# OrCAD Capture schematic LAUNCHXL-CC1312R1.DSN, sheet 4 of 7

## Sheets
4 3_Debugger Interface: size A3
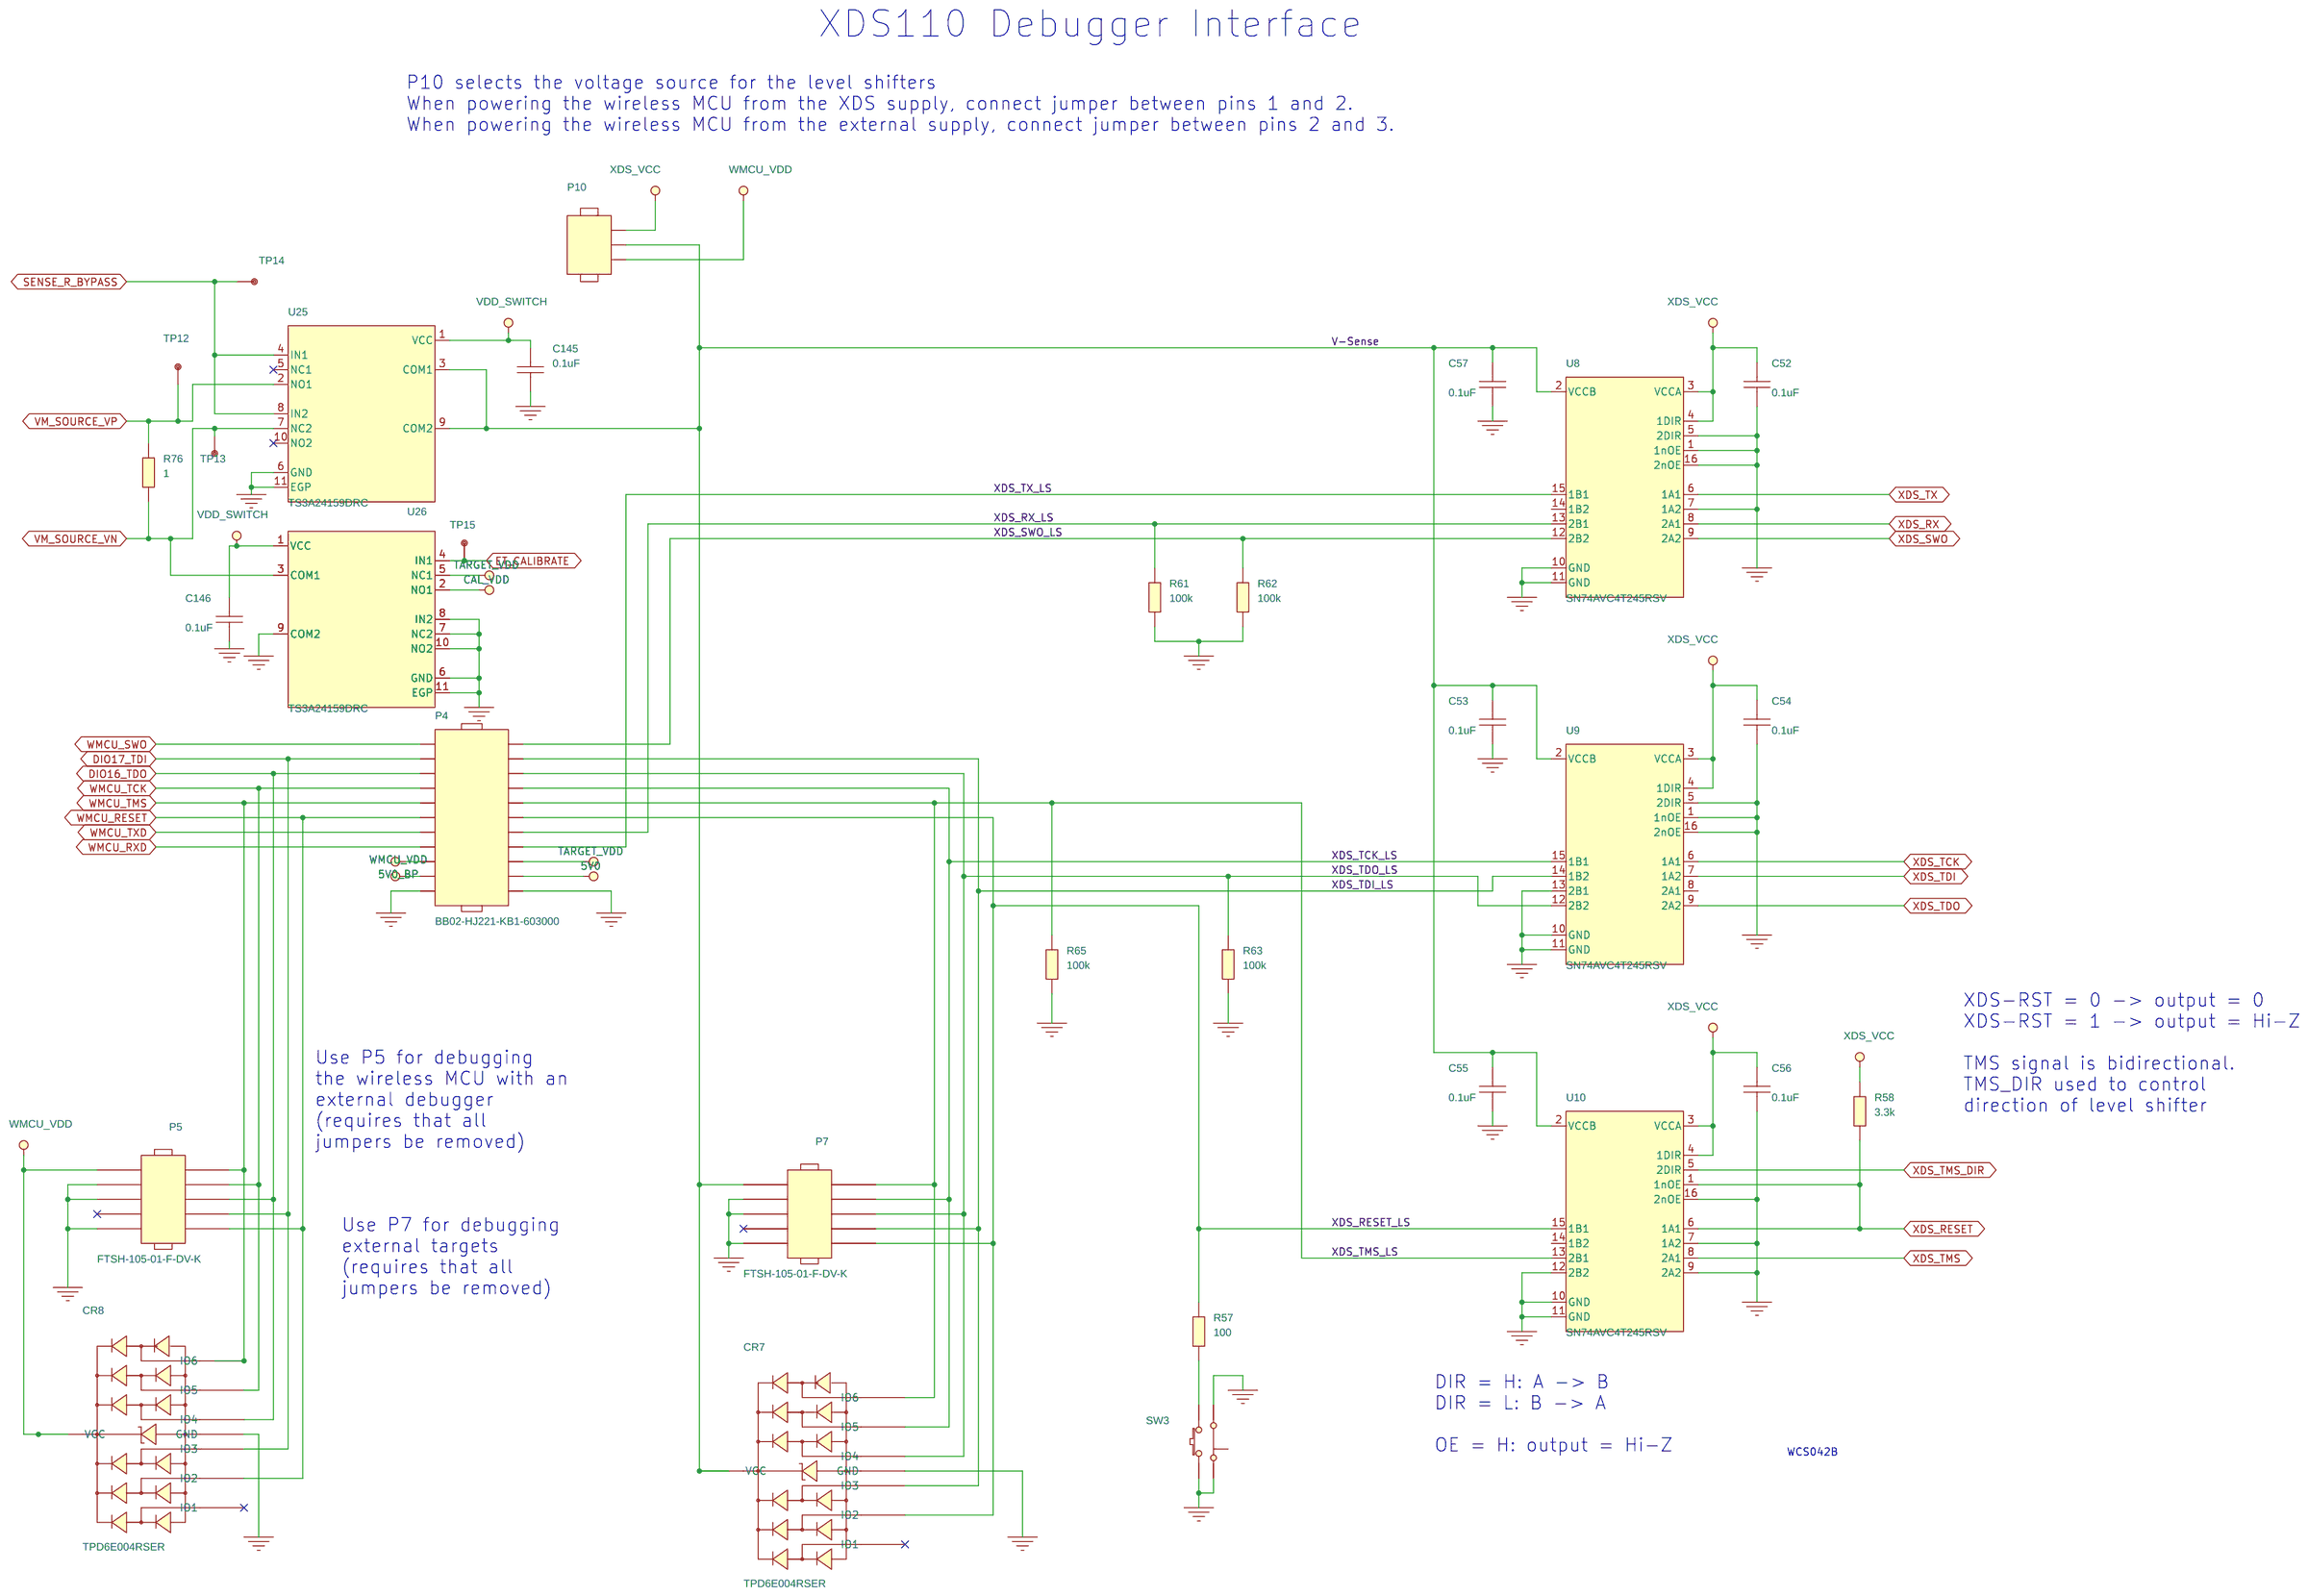
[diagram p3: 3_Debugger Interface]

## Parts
C52  0.1uF  [CAPC1005X60B2N]
C53  0.1uF  [CAPC1005X60B2N]
C54  0.1uF  [CAPC1005X60B2N]
C55  0.1uF  [CAPC1005X60B2N]
C56  0.1uF  [CAPC1005X60B2N]
C57  0.1uF  [CAPC1005X60B2N]
C145  0.1uF  [CAPC1005X60B2N]
C146  0.1uF  [CAPC1005X60B2N]
CR7  TPD6E004RSER  [QFN50P150X150X60-8N]
CR8  TPD6E004RSER  [QFN50P150X150X60-8N]
P4  BB02-HJ221-KB1-603000  [GRADCONN_BB02HJ221KB160300_A2B]
P5  FTSH-105-01-F-DV-K  [SAMTEC_FTSH-105-01-F-DV-K-10L]
P7  FTSH-105-01-F-DV-K  [SAMTEC_FTSH-105-01-F-DV-K-10L]
P10  BB02-HC031-KB1-603000  [GRADCONN_BB02HC031KB1603000_A2B]
R57  100  [RESC1005X40B2N]
R58  3.3k  [RESC1005X40B2N]
R61  100k  [RESC1005X40B2N]
R62  100k  [RESC1005X40B2N]
R63  100k  [RESC1005X40B2N]
R65  100k  [RESC1005X40B2N]
R76  1  [RESC3246X70A2N]
SW3  1188E-1K2-V  [SW_1188E1K2V_A2N]
TP12  HOLE_0.6mm_PTH  [MTG60_120]
TP13  HOLE_0.6mm_PTH  [MTG60_120]
TP14  HOLE_0.6mm_PTH  [MTG60_120]
TP15  HOLE_0.6mm_PTH  [MTG60_120]
U8  SN74AVC4T245RSV  [QFNFC40P180X260X55-16A2L]
U9  SN74AVC4T245RSV  [QFNFC40P180X260X55-16A2L]
U10  SN74AVC4T245RSV  [QFNFC40P180X260X55-16A2L]
U25  TS3A24159DRC  [SON50P300X300X100-11A2N]
U26  TS3A24159DRC  [SON50P300X300X100-11A2N]

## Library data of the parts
C52-C57 C145 C146 = CAPACITOR: CAPACITOR, CERAMIC X7R, 0.1uF, 25V, -10%/+10%, -55DEGC/+125DEGC, 0402, SMD; AutoDoc File: https://notefied-dynamic-precision.com/DB/Apps/Desktop/Item/Object.aspx?id=115293; BU Name: TEXAS INSTRUMENTS NORWAY; Client Status: UNDER_REVIEW; Datasheet URL 1: http://psearch.en.murata.com/capacitor/product/GRM155R71E104KE14%23.pdf; Datasheet URL 2: http://search.murata.co.jp/Ceramy/image/img/w_hinm/L0005E.pdf; Definied Quality: INDUSTRIAL; Dielectric Type: X7R; Esd Level: N/A; Last Time Buy: N/A; LifeCycle Status: ACTIVE; MPN: CAPACITOR_0402_100nF_X7R_M_+/-10%_10V; MPN Status: ACTIVE; MSL: N/A; MTBF: N/A; MTBF Standard: N/A; Manufacturer: MANUFACTURER SELECTION; Max Oper Temp: +125DEGC; Max Tol: +10%; Min Oper Temp: -55DEGC; Min Tol: -10%; Mounting Type: SMD; NOTE Status: PREFERRED; Old Footprint: CAPC1005X60N; PCB Package: 0402; Packing Size: 10000; Packing Type: TAPE_&_REEL; Part Number: 02-07861; Part Type: CAPACITOR\CERAMIC\0402\STANDARD; REACH/SVHC_COMPLIANCE: COMPLIANT; REACH/SVHC_DETAILS: SVHC LIST VERSION Jun 20, 2016; REACH/SVHC_SOURCE: REACH DECLARATION; REACH/SVHC_STATUS: UNAFFECTED; Revision: R002; RoHS Status: ROHS_COMPLIANT; Rtd Voltage: 25V; Vendor: MURATA; Vendor Part Number: GRM155R71E104KE14D; Vendor Part Status: ACTIVE; WEIGHT: 0.0016g
CR7 CR8 = DIODE_TVS_TPD6E004_QFN8_V1: DIODE, PROTECTION, ESD ARRAY - 6 CHANNELS, 7V, -40DEGC/+85DEGC, QFN8, SMD; ALT_SYMBOLS: QFN50P150X150X60-8L,QFN50P150X150X60-8M; AutoDoc File: https://notefied-dynamic-precision.com/DB/Apps/Desktop/Item/Object.aspx?id=74721; BU Name: DYNAMIC PRECISION GDANSK; Budget Currency: USD; Budget Price: 0.27; Client Status: UNDER_REVIEW; Country of Origin: UNITED STATES; Datasheet URL 1: http://www.ti.com/lit/ds/symlink/tpd6e004.pdf; Datasheet URL 2: http://www.ti.com/litv/pdf/mpqf207b; FPLIST: QFN50P150X150X60-8N,QFN50P150X150X60-8AN; Last Time Buy: N/A; Lead Time: 2; Max Oper Temp: +85DEGC; Min Oper Temp: -40DEGC; Mounting Type: SMD; PCB Package: QFN8; Packing Size: 3000; Packing Type: TAPE_&_REEL; Part Number: 14-05493; Part Type: DIODE\PROTECTION; Revision: R001; RoHS Status: ROHS_COMPLIANT; Rtd Power: N/A; Rtd Voltage: 7V; Vendor: TEXAS INSTRUMENTS; Vendor Part Status: ACTIVE; Weight: 0.0033g
P4 = CONN_HEADER_2X11_P_S: CONNECTOR, HEADER, MALE, STRAIGHT, 2 ROWS, 22 PINS, PITCH 2.54mm, PTH; ALT_SYMBOLS: GRADCONN_BB02HJ221KB160300_A2C,GRADCONN_BB02HJ221KB160300_A2A; AutoDoc File: http://notefied-dynamic-precision.com/DB/Apps/Desktop/Item/Object.aspx?id=105022; Datasheet URL 1: http://www.gradconn.com/Files/Drawings/BB02-HJ.pdf; Datasheet URL 2: http://www.gradconn.com/Files/Specs/BTB-2.54mm-Header-specification.pdf; Definied Quality: INDUSTRIAL; MPN Status: ACTIVE; Manufacturer: GRADCONN; Max Oper Temp: +105DEGC; Min Oper Temp: -40DEGC; Mounting Type: PTH; NOTE Status: PREFERRED; No Of Pos: 22; No Of Rows: 2; Part Number: 06-05049; Part Type: CONNECTOR\HEADER; Pitch: 2.54mm; Revision: R001; RoHS Status: ROHS_COMPLIANT; Rtd Current: 3A; Rtd Voltage: 600VAC
P5 P7 = CONN_HEADER_2X5: CONNECTOR, HEADER, MALE, STRAIGHT, 10 PINS, 2 ROWS, PITCH 1.27mm, SMD; ALT_SYMBOLS: SAMTEC_FTSH-105-01-F-DV-K-10L,SAMTEC_FTSH-105-01-F-DV-K-10M; AutoDoc File: http://notefied-dynamic-precision.com/DB/Apps/Desktop/Item/Object.aspx?id=50836; Budget Currency: USD; Budget Price: 1.700; Datasheet URL 1: http://www.samtec.com/documents/webfiles/cpdf/FTSH-1XX-XX-XXX-DV-XXX-MKT.pdf; Datasheet URL 2: http://www.samtec.com/documents/webfiles/pdf/FTSH_SMT.PDF; FPLIST: SAMTEC_FTSH-105-01-F-DV-K-10N,SAMTEC_FTSH-105-01-F-DV-K-10L,SAMTEC_FTSH-105-01-F-DV-K-10M; Lead Time: 2; LifeCycle Status: MATURITY; MPN Status: ACTIVE; Manufacturer: SAMTEC; Max Oper Temp: +125DEGC; Min Oper Temp: -55DEGC; Mounting Type: SMD; NOTE Status: PREFERRED; No Of Pos: 10; No Of Rows: 2; Old Footprint: SAMTEC_FTSH-105-01-F-DV-K-10N,CONN_MALE_2X5; Packing Size: 92; Packing Type: TUBE; Part Number: 06-00166; Part Type: CONNECTOR\HEADER; Pitch: 1.27mm; Revision: R003; RoHS Status: ROHS_COMPLIANT; Rtd Current: 1.75A; WEIGHT: 0.65614g
P10 = CONN_HEADER_3_P_S: CONNECTOR, HEADER, MALE, STRAIGHT, 1 ROW, 3 PINS, PITCH 2.54mm, PTH; ALT_SYMBOLS: GRADCONN_BB02HC031KB1603000_A2C,GRADCONN_BB02HC031KB1603000_A2A; AutoDoc File: http://notefied-dynamic-precision.com/DB/Apps/Desktop/Item/Object.aspx?id=104636; Datasheet URL 1: http://www.gradconn.com/Files/Drawings/BB02-HC.pdf; Datasheet URL 2: http://www.gradconn.com/Files/Specs/BTB-2.54mm-Header-specification.pdf; MPN Status: ACTIVE; Manufacturer: GRADCONN; Max Oper Temp: +105DEGC; Min Oper Temp: -40DEGC; Mounting Type: PTH; NOTE Status: PREFERRED; No Of Pos: 3; No Of Rows: 1; Part Number: 06-05038; Part Type: CONNECTOR\HEADER; Pitch: 2.54mm; Revision: R001; RoHS Status: ROHS_COMPLIANT; Rtd Current: 3A; Rtd Voltage: 250V
R57 = RESISTOR: RESISTOR, THICK FILM, 100, -5%/+5%, 0.063W, 50V, -55DEGC/+155DEGC, 0402, SMD; AutoDoc File: https://notefied-dynamic-precision.com/DB/Apps/Desktop/Item/Object.aspx?id=114555; BU Name: TEXAS INSTRUMENTS NORWAY; Budget Currency: USD; Budget Price: 0.0014; Client Status: UNDER_REVIEW; Country of Origin: UNITED STATES; Datasheet URL 1: http://www.vishay.com/docs/20035/dcrcwe3.pdf; Datasheet URL 2: N/A; Definied Quality: INDUSTRIAL; Esd Level: N/A; Last Time Buy: N/A; Lead Time: 16; LifeCycle Status: ACTIVE; MPN: RESISTOR_0402_100_+/-5%_50V_0.063W_M_+/-200ppm; MPN Status: ACTIVE; MSL: N/A; MTBF: N/A; MTBF Standard: N/A; Manufacturer: MANUFACTURER SELECTION; Max Oper Temp: +155DEGC; Max TC: +200PPM/DEGC; Max Tol: +5%; Min Oper Temp: -55DEGC; Min TC: -200PPM/DEGC; Min Tol: -5%; Mounting Type: SMD; NOTE Status: PREFERRED; Old Footprint: RESC1005X40N; PCB Package: 0402; Packing Size: 10000; Packing Type: TAPE_&_REEL; Part Number: 01-22482; Part Type: RESISTOR\0402\STANDARD; REACH/SVHC_COMPLIANCE: COMPLIANT; REACH/SVHC_DETAILS: SVHC LIST VERSION Jun 20, 2016; REACH/SVHC_SOURCE: MATERIAL DECLARATION; REACH/SVHC_STATUS: UNAFFECTED; Resistor Type: THICK FILM; Revision: R000; RoHS Status: ROHS_COMPLIANT; Rtd Current: N/A; Rtd Power: 0.063W; Rtd Voltage: 50V; Vendor: VISHAY; Vendor Part Number: CRCW0402100RJNED; Vendor Part Status: ACTIVE; WEIGHT: 0.00065g
R58 = RESISTOR: RESISTOR, THICK FILM, 3.3k, -5%/+5%, 0.063W, 50V, -55DEGC/+155DEGC, 0402, SMD; AutoDoc File: https://notefied-dynamic-precision.com/DB/Apps/Desktop/Item/Object.aspx?id=114561; BU Name: TEXAS INSTRUMENTS NORWAY; Budget Currency: EUR; Budget Price: 0.014; Client Status: UNDER_REVIEW; Country of Origin: ISRAEL; Datasheet URL 1: http://www.vishay.com/docs/20035/dcrcwe3.pdf; Datasheet URL 2: N/A; Definied Quality: INDUSTRIAL; Esd Level: N/A; Last Time Buy: N/A; Lead Time: 18; LifeCycle Status: ACTIVE; MPN: RESISTOR_0402_3.3k_+/-5%_50V_0.063W_M_+/-200ppm; MPN Status: ACTIVE; MSL: N/A; MTBF: N/A; MTBF Standard: N/A; Manufacturer: MANUFACTURER SELECTION; Max Oper Temp: +155DEGC; Max TC: +200PPM/DEGC; Max Tol: +5%; Min Oper Temp: -55DEGC; Min TC: -200PPM/DEGC; Min Tol: -5%; Mounting Type: SMD; NOTE Status: PREFERRED; Old Footprint: RESC1005X40N; PCB Package: 0402; Packing Size: 10000; Packing Type: TAPE_&_REEL; Part Number: 01-22488; Part Type: RESISTOR\0402\STANDARD; REACH/SVHC_COMPLIANCE: COMPLIANT; REACH/SVHC_DETAILS: SVHC LIST VERSION Jun 20, 2016; REACH/SVHC_SOURCE: MATERIAL DECLARATION; REACH/SVHC_STATUS: UNAFFECTED; Resistor Type: THICK FILM; Revision: R000; RoHS Status: ROHS_COMPLIANT; Rtd Current: N/A; Rtd Power: 0.063W; Rtd Voltage: 50V; Vendor: VISHAY; Vendor Part Number: CRCW04023K30JNED; Vendor Part Status: ACTIVE; WEIGHT: 0.00065g
R61-R63 R65 = RESISTOR: RESISTOR, THICK FILM, 100k, -1%/+1%, 0.063W, 50V, -55DEGC/+155DEGC, 0402, SMD; ALT_SYMBOLS: RESC1005X40B2L,RESC1005X40B2M; AutoDoc File: https://notefied-dynamic-precision.com/DB/Apps/Desktop/Item/Object.aspx?id=115161; BU Name: TEXAS INSTRUMENTS NORWAY; Client Status: UNDER_REVIEW; Datasheet URL 1: http://www.ttelectronicsresistors.com/datasheets/WCR.pdf; Definied Quality: INDUSTRIAL; Esd Level: N/A; LifeCycle Status: ACTIVE; MPN: RESISTOR_0402_100k_+/-1%_50V_0.063W_M_+/-100PPM; MPN Status: ACTIVE; MSL: N/A; MTBF: N/A; MTBF Standard: N/A; Manufacturer: MANUFACTURER SELECTION; Max Oper Temp: +155DEGC; Max TC: +100PPM/DEGC; Max Tol: +1%; Min Oper Temp: -55DEGC; Min TC: -100PPM/DEGC; Min Tol: -1%; Mounting Type: SMD; NOTE Status: PREFERRED; Old Footprint: RESC1005X40N; PCB Package: 0402; Packing Size: 10000; Packing Type: TAPE_&_REEL; Part Number: 01-22536; Part Type: RESISTOR\0402\PRECISION; Resistor Type: THICK FILM; Revision: R001; RoHS Status: ROHS_COMPLIANT; Rtd Current: N/A; Rtd Power: 0.063W; Rtd Voltage: 50V; Vendor: TT ELECTRONICS; Vendor Part Number: WCR0402-100KFA; Vendor Part Status: ACTIVE
R76 = RESISTOR: RESISTOR, THICK FILM, 1, -1%/+1%, 1W, 200V, -55DEGC/+155DEGC, 1218, SMD; ALT_SYMBOLS: RESC3246X70A2L,RESC3246X70A2M; AutoDoc File: https://notefied-dynamic-precision.com/DB/Apps/Desktop/Item/Object.aspx?id=58334; BU Name: DYNAMIC PRECISION GDANSK; Budget Currency: USD; Budget Price: 0.1485; Client Status: UNDER_REVIEW; Country of Origin: ISRAEL; Datasheet URL 1: http://www.vishay.com/docs/20035/dcrcwe3.pdf; Datasheet URL 2: N/A; Last Time Buy: N/A; Lead Time: 10; Max Oper Temp: +155DEGC; Max TC: +200PPM/DEGC; Max Tol: +1%; Min Oper Temp: -55DEGC; Min TC: -200PPM/DEGC; Min Tol: -1%; Mounting Type: SMD; PCB Package: 1218; Packing Size: 4000; Packing Type: TAPE_&_REEL; Part Number: 01-03527; Part Type: RESISTOR\1218\PRECISION; Resistor Type: THICK FILM; Revision: R003; RoHS Status: ROHS_COMPLIANT_WITH_EXEMPTION; Rtd Current: N/A; Rtd Power: 1W; Rtd Voltage: 200V; Vendor: VISHAY; Vendor Part Number: CRCW12181R00FNEK; Vendor Part Status: ACTIVE; Weight: 0.0295g
SW3 = SWITCH_TACT_V2: SWITCH, TACT, 0.05A@250VAC, 0.05A@12VDC, 0.05A, 250V, SMD; ALT_SYMBOLS: SW_1188E1K2V_A2L,SW_1188E1K2V_A2M; AutoDoc File: http://notefied-dynamic-precision.com/DB/Apps/Desktop/Item/Object.aspx?id=104642; Datasheet URL 1: N/A; Datasheet URL 2: http://www.dip.com.tw/en/en-product-information/en-switch004; FPLIST: SW_1188E1K2V_A2N,SW_1188E1K2V_A2L,SW_1188E1K2V_A2M; MPN: 1188E-1K2-V-TR; MPN Status: ACTIVE; Manufacturer: DIPTRONICS; Max Oper Temp: +70DEGC; Min Oper Temp: -25DEGC; Mounting Type: SMD; NOTE Status: PREFERRED; Packing Size: 1500; Packing Type: TAPE_&_REEL; Part Number: 08-00293; Part Type: SWITCH\TACT; Revision: R001; RoHS Status: ROHS_COMPLIANT; Rtd Current: 0.05A; Rtd Voltage: 12V
TP12-TP15 = HOLE_PTH: NON COMPONENT, HOLE 0.6mm, PLATED HOLE; AutoDoc File: https://notefied-dynamic-precision.com/DB/Apps/Desktop/Item/Object.aspx?id=57336; BU Name: DYNAMIC PRECISION GDANSK; Part Number: 19-00057; Part Type: NON_COMPONENT\HOLE\PLATED; Revision: R001
U8-U10 = IC_XCVR_SN74AVC4T245_UQFN16_2: IC, DIGITAL, LOGIC, 4bit DUAL-SUPPLY BUS TRANSCEIVER 3 STATE OUTPUT, 1.2V TO 3.6V, UQFN16, SMD; ALT_SYMBOLS: QFNFC40P180X260X55-16A2L,QFNFC40P180X260X55-16A2M; AutoDoc File: http://notefied-dynamic-precision.com/DB/Apps/Desktop/Item/Object.aspx?id=95718; Budget Currency: USD; Budget Price: 0.39; Datasheet URL 1: http://www.ti.com/litv/pdf/mpqf205c; Datasheet URL 2: http://www.ti.com/lit/ds/symlink/sn74avc4t245.pdf; Definied Quality: INDUSTRIAL; FPLIST: QFNFC40P180X260X55-16A2N,QFNFC40P180X260X55-16A2L,QFNFC40P180X260X55-16A2M; Last Time Buy: N/A; Lead Time: 8; LifeCycle Status: ACTIVE; MPN: SN74AVC4T245RSVR; MPN Status: ACTIVE; MSL: 1; Manufacturer: TEXAS INSTRUMENTS; Max Oper Temp: +85DEGC; Min Oper Temp: -40DEGC; Mounting Type: SMD; NOTE Status: PREFERRED; Old Footprint: QFNFC40P180X260X55-16A2N; PCB Package: UQFN16; Packing Size: 3000; Packing Type: TAPE_&_REEL; Part Number: 18-29288; Part Type: IC\DIGITAL\LOGIC\TRANSCEIVER; Revision: R002; RoHS Status: ROHS_COMPLIANT; Rtd Voltage: 1.2V TO 3.6V; WEIGHT: 0.0062g
U25 U26 = IC_SWITCH_TS3A24159_SON10: IC, ANALOG, 0.3R DUAL SPDT ANALOG SWITCH DUAL-CHANNEL 2:1 MULTIPLEXER/DEMULTIPLEXER, 1.65V TO 3.6V, SON10-EP, SMD; ALT_SYMBOLS: SON50P300X300X100-11A2L,SON50P300X300X100-11A2M; AutoDoc File: https://notefied-dynamic-precision.com/DB/Apps/Desktop/Item/Object.aspx?id=99151; BU Name: DYNAMIC PRECISION GDANSK; Budget Currency: USD; Budget Price: 0.35; Client Status: UNDER_REVIEW; Country of Origin: MALAYSIA; Datasheet URL 1: http://www.ti.com/lit/ds/symlink/ts3a24159.pdf; Datasheet URL 2: http://www.ti.com/litv/pdf/mpds117k; Last Time Buy: N/A; Lead Time: 2; Max Oper Temp: +85DEGC; Min Oper Temp: -40DEGC; Mounting Type: SMD; PCB Package: SON10-EP; Packing Size: 3000; Packing Type: TAPE_&_REEL; Part Number: 18-30805; Part Type: IC\ANALOG\SWITCH; Revision: R001; RoHS Status: ROHS_COMPLIANT; Rtd Voltage: 1.65V TO 3.6V; Vendor: TEXAS INSTRUMENTS; Vendor Part Number: TS3A24159DRCR; Vendor Part Status: ACTIVE; Weight: 0.0248g

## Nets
5V0: P4.19 ; also on sheet 1 5
5V0_BP: P4.20 ; also on sheet 6
GND: C52.2 C53.2 C54.2 C55.2 C56.2 C57.2 C145.2 C146.2 CR7.4(GND) CR8.4(GND) P4.21 P4.22 P5.3 P5.5 P5.9 P7.3 P7.5 P7.9 R61.1 R62.1 R63.1 R65.1 SW3.1 SW3.2 SW3.4 U8.1(1nOE) U8.5(2DIR) U8.7(1A2) U8.10(GND) U8.11(GND) U8.16(2nOE) U9.1(1nOE) U9.5(2DIR) U9.10(GND) U9.11(GND) U9.13(2B1) U9.16(2nOE) U10.7(1A2) U10.9(2A2) U10.10(GND) U10.11(GND) U10.12(2B2) U10.16(2nOE) U25.6(GND) U25.11(EGP) U26.6(GND) U26.7(NC2) U26.8(IN2) U26.9(COM2) U26.10(NO2) U26.11(EGP) ; also on sheet 1 2 3 5 6 7
VDD_SWITCH: C145.1 C146.1 U25.1(VCC) U26.1(VCC) ; also on sheet 1 2
CAL_VDD: U26.2(NO1) ; also on sheet 2
DIO16_TDO: CR8.5(IO4) P4.6 P5.6 ; also on sheet 6
DIO17_TDI: CR8.3(IO3) P4.4 P5.8 ; also on sheet 6
ET_CALIBRATE: TP15.1 U26.4(IN1) ; also on sheet 5
SENSE_R_BYPASS: TP14.1 U25.4(IN1) U25.8(IN2) ; also on sheet 5
TARGET_VDD: P4.17 U26.5(NC1)
V-Sense: C53.1 C55.1 C57.1 CR7.8(VCC) P7.1 P10.2 U8.2(VCCB) U9.2(VCCB) U10.2(VCCB) U25.3(COM1) U25.9(COM2)
VM_SOURCE_VN: R76.1 TP13.1 U25.7(NC2) U26.3(COM1) ; also on sheet 2
VM_SOURCE_VP: R76.2 TP12.1 U25.2(NO1) ; also on sheet 2
WMCU_RESET: CR8.2(IO2) P4.12 P5.10 ; also on sheet 6 7
WMCU_RXD: P4.16 ; also on sheet 6
WMCU_SWO: P4.2 ; also on sheet 6
WMCU_TCK: CR8.6(IO5) P4.8 P5.4 ; also on sheet 6 7
WMCU_TMS: CR8.7(IO6) P4.10 P5.2 ; also on sheet 6 7
WMCU_TXD: P4.14 ; also on sheet 6
WMCU_VDD: CR8.8(VCC) P4.18 P5.1 P10.3 ; also on sheet 6 7
XDS_RESET: R58.1 U10.1(1nOE) U10.6(1A1) ; also on sheet 5
XDS_RESET_LS: CR7.2(IO2) P4.11 P7.10 R57.2 U10.15(1B1)
XDS_RX: U8.8(2A1) ; also on sheet 5
XDS_RX_LS: P4.13 R61.2 U8.13(2B1)
XDS_SWO: U8.9(2A2) ; also on sheet 5
XDS_SWO_LS: P4.1 R62.2 U8.12(2B2)
XDS_TCK: U9.6(1A1) ; also on sheet 5
XDS_TCK_LS: CR7.6(IO5) P4.7 P7.4 U9.15(1B1)
XDS_TDI: U9.7(1A2) ; also on sheet 5
XDS_TDI_LS: CR7.3(IO3) P4.3 P7.8 U9.14(1B2)
XDS_TDO: U9.9(2A2) ; also on sheet 5
XDS_TDO_LS: CR7.5(IO4) P4.5 P7.6 R63.2 U9.12(2B2)
XDS_TMS: U10.8(2A1) ; also on sheet 5
XDS_TMS_DIR: U10.5(2DIR) ; also on sheet 5
XDS_TMS_LS: CR7.7(IO6) P4.9 P7.2 R65.2 U10.13(2B1)
XDS_TX: U8.6(1A1) ; also on sheet 5
XDS_TX_LS: P4.15 U8.15(1B1)
XDS_VCC: C52.1 C54.1 C56.1 P10.1 R58.2 U8.3(VCCA) U8.4(1DIR) U9.3(VCCA) U9.4(1DIR) U10.3(VCCA) U10.4(1DIR) ; also on sheet 5
N1384129: R57.1 SW3.3

Not connected (* = marked no-connect by the designer): CR7 1(IO1)*; CR8 1(IO1)*; P5 7*; P7 7*; U8 14(1B2); U9 8(2A1); U10 14(1B2); U25 5(NC1)* 10(NO2)*

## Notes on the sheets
sheet 4
- XDS110 Debugger Interface
- P10 selects the voltage source for the level shifters
  When powering the wireless MCU from the XDS supply, connect jumper between pins 1 and 2.
  When powering the wireless MCU from the external supply, connect jumper between pins 2 and 3.
- XDS-RST = 0 -> output = 0
  XDS-RST = 1 -> output = Hi-Z
  TMS signal is bidirectional.
  TMS_DIR used to control
  direction of level shifter
- Use P5 for debugging
  the wireless MCU with an
  external debugger
  (requires that all
  jumpers be removed)
- Use P7 for debugging
  external targets
  (requires that all
  jumpers be removed)
- DIR = H: A -> B
  DIR = L: B -> A
  OE = H: output = Hi-Z
- WCS042B
